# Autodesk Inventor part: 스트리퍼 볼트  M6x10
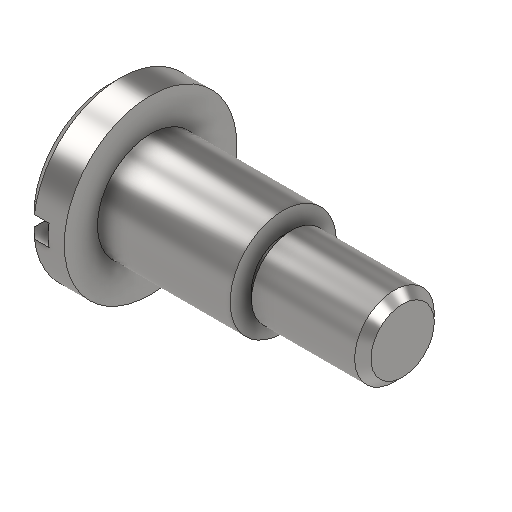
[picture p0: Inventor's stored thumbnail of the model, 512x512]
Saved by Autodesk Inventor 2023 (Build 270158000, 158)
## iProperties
Created: 2025-02
Part Number: 스트리퍼 볼트  M6x10
Material: 강철, 연강
Description: 홈붙이 냄비머리 나사
Document SubType Name: Modeling
Designer: home
Density: 7.85 g/cm^3
Appearance: 기본값
Author: jhkim
Sending System: Autodesk Inventor 2025
Preprocessor: ST-DEVELOPER v20
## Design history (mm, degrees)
node "스트리퍼 볼트 M6x101"
node "솔리드1"
body "Solid1"
